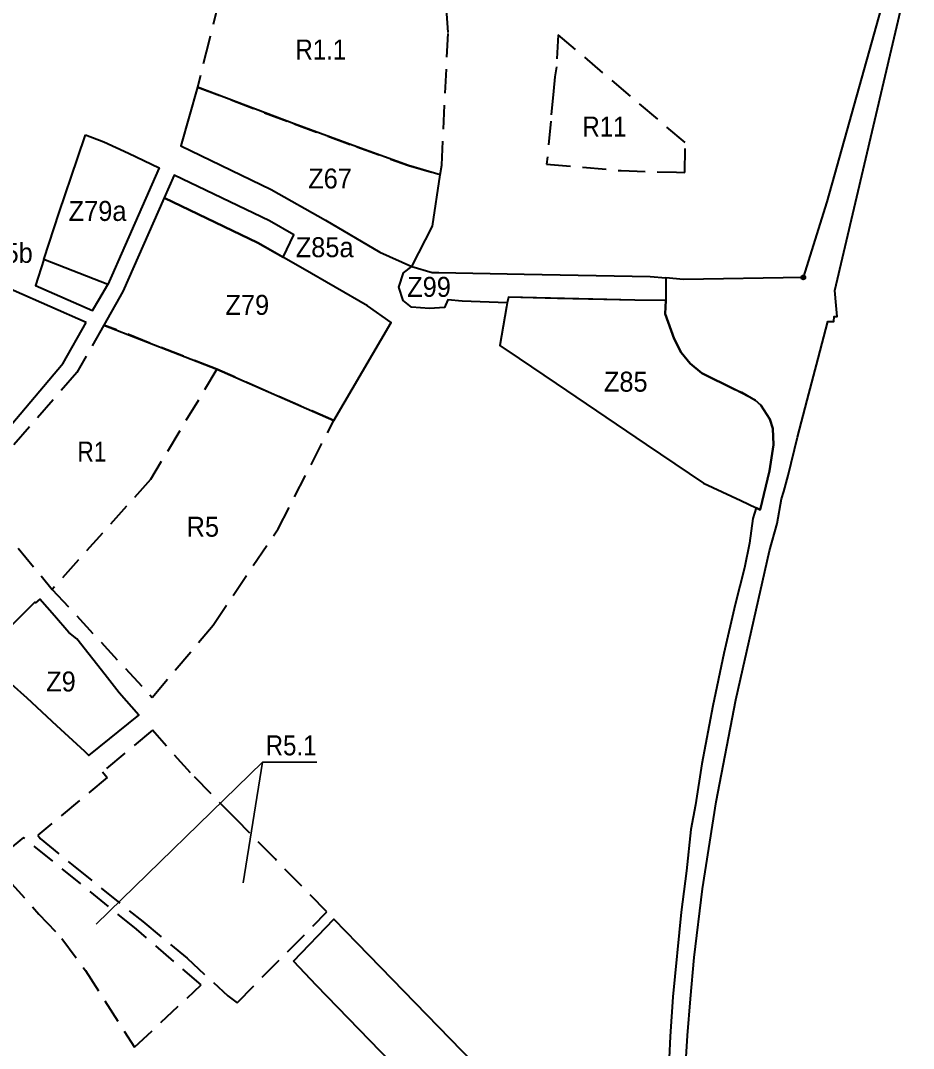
# Model space of a CAD drawing. Extents: x -650276 to -642489, y -1074311 to -1066658.
# Drawn here: x -646145 to -645072, y -1072295 to -1071059 of the extents above; entities that cross this region are included whole.
import ezdxf

# ---------------------------------------------------------------- set-up
doc = ezdxf.new("R2010")
doc.units = 0
doc.header["$LTSCALE"] = 9.6
doc.header["$PDMODE"] = 32
doc.header["$PDSIZE"] = 4.8
doc.linetypes.add('MEDIUM_DASHED', pattern=[4.5, 3, -1.5])
for name, color, linetype, lineweight in [('44', 7, 'Continuous', 40), ('45', 7, 'Continuous', 40), ('46', 7, 'Continuous', 13), ('61', 7, 'MEDIUM_DASHED', 40), ('62', 7, 'Continuous', 35)]:
    doc.layers.add(name, color=color, linetype=linetype, lineweight=lineweight)

msp = doc.modelspace()

# ---------------------------------------------------------------- linework, layer by layer
at = {"layer": '44'}
msp.add_line((-645369.665, -1071395.694), (-645370.24, -1071411.83), dxfattribs=at)
for points in [[(-645078.23, -1070915.65), (-645092.67, -1070979.52), (-645176.14, -1071277.26), (-645204.341, -1071368.19)], [(-645166.34, -1071384.07), (-645071.99, -1070980.72)], [(-645407.045, -1071395.646), (-645499.65, -1071393.3), (-645558.872, -1071391.801), (-645560.11, -1071398.7), (-645614.201, -1071396.844), (-645631.44, -1071394.9), (-645635.795, -1071404.403), (-645653.742, -1071405.36), (-645675.177, -1071403.922), (-645685.098, -1071395.824), (-645690.677, -1071379.721), (-645684.785, -1071362.539), (-645674.947, -1071355.071), (-645650.28, -1071362.07), (-645642.431, -1071362.259), (-645539.738, -1071364.092)], [(-645539.738, -1071364.092), (-645388.619, -1071366.991), (-645369.696, -1071368.676)], [(-645369.67, -1071368.678), (-645369.665, -1071395.694), (-645407.045, -1071395.646)], [(-645204.341, -1071368.19), (-645348.55, -1071370.559), (-645369.67, -1071368.678)], [(-645222.48, -1071606.08), (-645211.27, -1071560.01), (-645199.61, -1071515.68), (-645186.67, -1071465.55), (-645175.06, -1071420.93), (-645167.58, -1071421.19), (-645167.37, -1071415.2), (-645163.56, -1071415.3), (-645164.76, -1071401.79), (-645166.34, -1071384.07)], [(-645370.24, -1071411.83), (-645369.665, -1071395.694), (-645407.045, -1071395.646), (-645558.872, -1071391.801), (-645560.11, -1071398.7), (-645560.94, -1071403.441)], [(-645560.94, -1071403.441), (-645569.07, -1071449.88), (-645545.817, -1071465.611)], [(-645370.24, -1071411.83), (-645359.64, -1071442), (-645351.06, -1071458.3), (-645340.16, -1071471.63), (-645326.29, -1071483.41), (-645286.62, -1071502.67), (-645278.52, -1071506.12)], [(-645326.29, -1071483.41), (-645340.16, -1071471.63), (-645351.06, -1071458.3), (-645359.64, -1071442), (-645370.24, -1071411.83)], [(-645545.817, -1071465.611), (-645501.37, -1071495.68), (-645393.34, -1071568.75)], [(-645279.531, -1071636.404), (-645261.094, -1071645.025), (-645256.02, -1071647.398), (-645244.81, -1071600.61), (-645240.26, -1071569.52), (-645240.82, -1071549.6), (-645244.4, -1071538.48), (-645255.51, -1071521.55), (-645262.36, -1071515.72), (-645286.62, -1071502.67), (-645326.29, -1071483.41)], [(-645278.52, -1071506.12), (-645262.36, -1071515.72), (-645255.51, -1071521.55), (-645244.4, -1071538.48), (-645240.82, -1071549.6), (-645240.26, -1071569.52), (-645244.81, -1071600.61), (-645256.02, -1071647.398), (-645261.094, -1071645.025)], [(-645393.34, -1071568.75), (-645324.17, -1071615.53), (-645279.531, -1071636.404)], [(-645347.551, -1072443.527), (-645347.677, -1072391.355), (-645346.62, -1072330.914), (-645343.458, -1072278.998), (-645339.908, -1072235.158), (-645335.367, -1072185.207), (-645325.498, -1072102.789), (-645309.01, -1071998.147), (-645285.617, -1071875.733), (-645244.798, -1071696.585), (-645235.793, -1071663.703), (-645230.436, -1071634.261), (-645227.905, -1071625.277), (-645222.48, -1071606.08)], [(-645261.094, -1071645.025), (-645264.841, -1071657.687), (-645269.077, -1071687.396), (-645274.868, -1071717.176), (-645286.175, -1071761.228), (-645300.076, -1071820.179), (-645313.153, -1071883.081)], [(-645313.153, -1071883.081), (-645326.343, -1071952.807), (-645334.118, -1072001.954), (-645339.455, -1072031.565), (-645344.819, -1072081.225), (-645351.358, -1072130.815), (-645361.317, -1072232.824), (-645364.435, -1072280.268), (-645366.951, -1072331.609), (-645370.624, -1072401.447), (-645372.228, -1072438.764)]]:
    msp.add_lwpolyline(points, dxfattribs=at)
for points in [[(-645829.706, -1071343.963), (-645816.714, -1071316.828), (-645846, -1071300), (-645960.34, -1071245.09), (-645972.422, -1071272.568), (-645859.986, -1071326.563)], [(-646117.031, -1071346.48), (-646127.301, -1071378.036), (-646058.719, -1071407.796), (-646051.148, -1071395.208), (-646040.084, -1071376.813)]]:
    msp.add_lwpolyline(points, close=True, dxfattribs=at)
msp.add_point((-645204.341, -1071368.19), dxfattribs=at)
at = {"layer": '45'}
for points in [[(-645674.947, -1071355.071), (-645650.09, -1071306.433), (-645640.737, -1071244.963), (-645678.86, -1071233.58), (-645741.09, -1071211.36), (-645816.47, -1071183.63), (-645932.502, -1071139.426), (-645952.419, -1071210.117), (-645844.079, -1071262.487), (-645778.69, -1071299.362), (-645713.428, -1071337.765)], [(-646067.097, -1071196.699), (-646044.944, -1071205.157), (-646015.387, -1071218.854), (-645978.403, -1071236.481), (-646023.652, -1071339.428), (-646035.241, -1071365.795), (-646040.084, -1071376.813), (-646117.031, -1071346.48), (-646098.66, -1071290.03), (-646076.713, -1071225.138)], [(-645768.62, -1071540.17), (-645699.825, -1071422.134), (-645728.054, -1071402.382), (-645806.036, -1071357.564), (-645859.986, -1071326.563), (-645972.422, -1071272.568), (-646022.073, -1071385.273), (-646044.948, -1071425.333), (-645909.13, -1071478.56)], [(-645768.62, -1071540.17), (-645699.825, -1071422.134), (-645728.054, -1071402.382), (-645806.036, -1071357.564), (-645859.986, -1071326.563), (-645972.422, -1071272.568), (-646022.073, -1071385.273), (-646044.948, -1071425.333), (-645909.13, -1071478.56)], [(-646066.165, -1071422.155), (-646153.5, -1071383.85), (-646208.577, -1071360.044), (-646241.68, -1071416.887), (-646258.487, -1071439.265), (-646275.615, -1071460.886), (-646289.976, -1071477.514), (-646330.914, -1071521.11), (-646324, -1071535), (-646217.978, -1071613.552), (-646211.407, -1071606.247), (-646156.471, -1071545.166), (-646094.063, -1071471.007)], [(-646066.165, -1071422.155), (-646153.5, -1071383.85), (-646208.577, -1071360.044), (-646241.68, -1071416.887), (-646258.487, -1071439.265), (-646275.615, -1071460.886), (-646289.976, -1071477.514), (-646330.914, -1071521.11), (-646324, -1071535), (-646217.978, -1071613.552), (-646211.407, -1071606.247), (-646156.471, -1071545.166), (-646094.063, -1071471.007)], [(-646102.04, -1071906.4), (-646068.317, -1071937.555), (-646062.91, -1071942.55), (-646002.93, -1071893.984), (-646026.64, -1071867.44), (-646043.49, -1071845.87), (-646077.32, -1071802.59), (-646087, -1071795), (-646104.5, -1071774.86), (-646122.16, -1071754.78), (-646127.12, -1071759.15), (-646127.84, -1071758.53), (-646191.57, -1071821.44), (-646174.69, -1071838.69), (-646156.59, -1071856.53), (-646137.74, -1071873.31)], [(-645817.219, -1072189.975), (-645768.649, -1072139.283), (-645740.45, -1072168.23), (-645559.34, -1072354.42), (-645546.82, -1072365.72), (-645550.41, -1072368.47), (-645636.37, -1072379.57), (-645650.78, -1072342.73), (-645674, -1072338), (-645789.298, -1072218.833)]]:
    msp.add_lwpolyline(points, close=True, dxfattribs=at)
at = {"layer": '61'}
msp.add_line((-645909.13, -1071478.56), (-646044.948, -1071425.333), dxfattribs=at)
for points in [[(-645881.661, -1070953.494), (-645885.966, -1070952.452), (-645918.57, -1071083.449), (-645932.502, -1071139.426), (-645816.47, -1071183.63), (-645741.09, -1071211.36), (-645678.86, -1071233.58), (-645640.737, -1071244.963), (-645638.935, -1071233.122), (-645631.241, -1071073.956), (-645635.256, -1071013.15)], [(-645512.84, -1071231.9), (-645423.08, -1071239.85), (-645356.794, -1071241.776), (-645346.67, -1071242.07), (-645346.31, -1071206.07), (-645498.931, -1071076.631), (-645500.94, -1071115.24), (-645503.08, -1071126.98), (-645504.79, -1071144.18), (-645507.84, -1071180.326)], [(-645909.13, -1071478.56), (-645989, -1071611), (-646107, -1071743), (-645987.026, -1071872.902), (-645913.616, -1071786.041), (-645835.644, -1071670.191), (-645768.62, -1071540.17)], [(-645896.15, -1072231.57), (-645884.949, -1072239.96), (-645777.057, -1072130.664), (-645839.31, -1072066.947), (-645885.655, -1072019.486), (-645940.8, -1071963.54), (-645986.568, -1071912.301), (-646046.78, -1071962.265), (-646041.113, -1071969.094), (-646124.568, -1072038.344), (-646121.403, -1072042.471), (-646081.78, -1072075), (-645998.22, -1072142.19), (-645945, -1072186)], [(-646141.703, -1072041.072), (-646178.915, -1072071.95), (-646159.66, -1072092.31), (-646123.06, -1072133.18), (-646095.44, -1072162.47), (-646067.08, -1072201.18), (-646008.065, -1072293.22), (-645928.101, -1072218.151), (-646005.793, -1072151.499)]]:
    msp.add_lwpolyline(points, close=True, dxfattribs=at)
msp.add_lwpolyline([(-646044.948, -1071425.333), (-646077.593, -1071482.499), (-646203.387, -1071627.322), (-646107, -1071743)], dxfattribs=at)
at = {"layer": '62'}
msp.add_line((-645854.421, -1071950.737), (-645877.767, -1072095.485), dxfattribs=at)
msp.add_lwpolyline([(-645789.051, -1071950.737), (-645854.421, -1071950.737), (-646054.422, -1072145.291)], dxfattribs=at)

# ---------------------------------------------------------------- texts
at = {"layer": '44', "width": 0.95}
for s, p in [('Z85b', (-646199.969, -1071350.698)), ('Z85a', (-645814.405, -1071343.847)), ('Z85a', (-645814.405, -1071343.847)), ('Z99', (-645680.485, -1071391.504)), ('Z99', (-645680.485, -1071391.504)), ('Z85', (-645444.048, -1071505.433)), ('Z85', (-645444.048, -1071505.433))]:
    msp.add_text(s, height=24, dxfattribs=at).set_placement(p)
at = {"layer": '46', "width": 0.95}
for s, p in [('Z67', (-645799.458, -1071261.304)), ('Z67', (-645799.458, -1071261.304)), ('Z79a', (-646087.322, -1071300.282)), ('Z79', (-645898.897, -1071413.165)), ('Z79', (-645898.897, -1071413.165)), ('Z9', (-646114.385, -1071865.725))]:
    msp.add_text(s, height=24, dxfattribs=at).set_placement(p)
at = {"layer": '62'}
for s, width, p in [('R1.1', 0.9, (-645814.758, -1071106.298)), ('R11', 0.9, (-645469.881, -1071198.853)), ('R1', 0.85, (-646076.842, -1071589.396)), ('R5', 0.95, (-645945.557, -1071679.725)), ('R5', 0.95, (-645945.557, -1071679.725)), ('R5.1', 0.9, (-645850.499, -1071942.459))]:
    msp.add_text(s, height=24, dxfattribs=dict(at, width=width)).set_placement(p)

doc.saveas('drawing.dxf')
